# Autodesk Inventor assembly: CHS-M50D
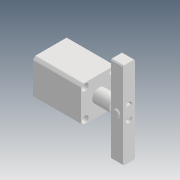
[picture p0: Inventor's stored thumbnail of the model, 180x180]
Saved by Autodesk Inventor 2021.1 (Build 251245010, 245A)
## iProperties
Created: 2019-04
Part Number: CHS-M50D
Description: STEP AP203
Document SubType Name: Assembly
Designer: user
Title: chs-m50d_asm.STEP
Revision Number: ÈÎºÎ
Sending System: SolidWorks 2017
Preprocessor: SwSTEP 2.0
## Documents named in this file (6)
- D:\Vault_2016\Projekty\Clamptek\Hydraulic\CHS\CHS-50\Inventor\CHS-M50D\CHS-M50D.iam
- D:\Vault_2016\Projekty\Clamptek\Hydraulic\CHS\CHS-50\Inventor\CHS-M50D\CHS-M50BT.ipt
- D:\Vault_2016\Projekty\Clamptek\Hydraulic\CHS\CHS-50\Inventor\CHS-M50D\CHS-50DHSG_3.ipt
- D:\Vault_2016\Projekty\Clamptek\Hydraulic\CHS\CHS-50\Inventor\CHS-M50D\CHS-50DYB_4.ipt
- D:\Vault_2016\Projekty\Clamptek\Hydraulic\CHS\CHS-50\Inventor\CHS-M50D\Ïú.ipt
- D:\Vault_2016\Projekty\Clamptek\Hydraulic\CHS\CHS-50\Inventor\CHS-M50D\ÖáÓÃµ²È¦.ipt
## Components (6 placed, 6 different names)
1. CHS-M50BT_1
2. CHS-50DHSG_3_2
3. CHS-50DYB_4_3
4. Ïú_4
5. ÖáÓÃµ²È¦_5
6. ÖáÓÃµ²È¦_6
